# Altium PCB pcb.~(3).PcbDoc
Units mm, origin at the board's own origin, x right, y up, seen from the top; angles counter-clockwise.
Board outline 11.94 x 11.05 mm, 2 copper layers (Top Layer, Bottom Layer); 9 components, 6 nets, 43 pads, 0 vias.
Unrouted connection lines stored in the file: 24.
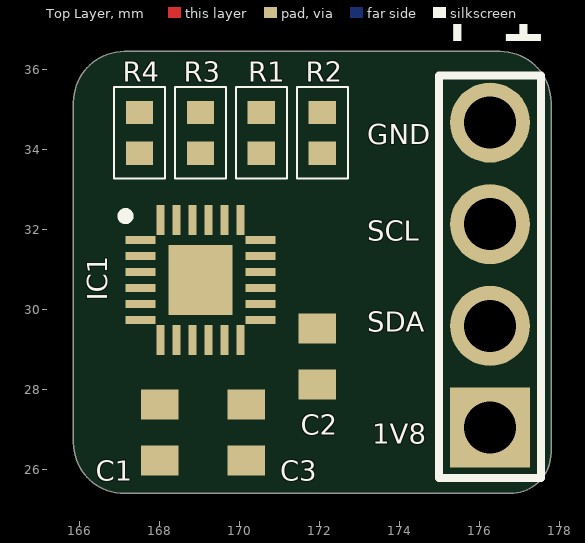
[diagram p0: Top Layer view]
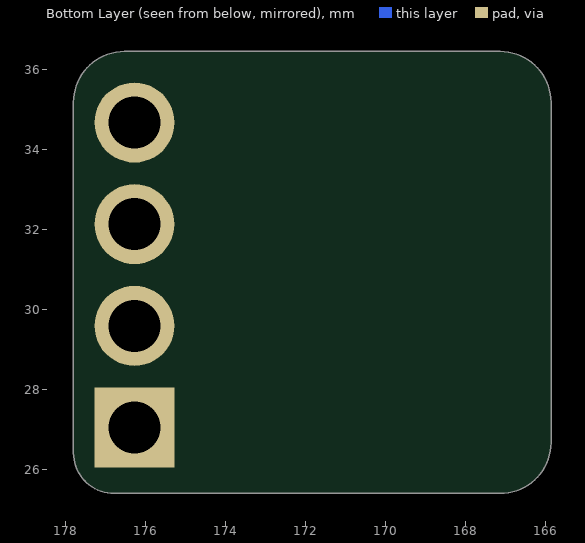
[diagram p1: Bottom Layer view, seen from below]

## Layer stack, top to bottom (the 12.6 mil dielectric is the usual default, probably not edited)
Top Solder: solder mask 0.0102, Solder Resist, Dk 3.5
Top Layer: signal copper 0.0356
Dielectric 1: dielectric 0.32, FR-4, Dk 4.8
Bottom Layer: signal copper 0.0356
Bottom Solder: solder mask 0.0102, Solder Resist, Dk 3.5

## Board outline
165.862,26.67 ccw(c167.132,26.67) 167.132,25.4 176.784,25.4 ccw(c176.784,26.416) 177.8,26.416 177.8,35.179 ccw(c176.53,35.179) 176.53,36.449 167.132,36.449 ccw(c167.132,35.179) 165.862,35.179

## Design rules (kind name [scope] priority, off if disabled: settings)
Clearance [All] p1: gap=0.254 ignorepadtopadclearanceinfootprint=FALSE
PolygonConnect [All] p1: connectstyle=Relief reliefconductorwidth=0.254 reliefentries=4 polygonreliefangle="90 Angle" airgapwidth=0.254
RoutingVias [All] p1: holewidth=0.711 width=1.27 viastyle="Through Hole" minholewidth=0.711 minwidth=1.27 maxholewidth=0.711 maxwidth=1.27
SolderMaskExpansion [All] p1: expansion=0.102 istentingtop=FALSE
SupplyNets "Schematic Supply Nets_1" [InNet('1V8')] p1: voltage=0.000
SupplyNets "Schematic Supply Nets" [InNet('GND')] p2: voltage=0.000
Width [All] p1: maxlimit=0.254 minlimit=0.254 preferedwidth=0.254
30 further rules are at their usual default settings.

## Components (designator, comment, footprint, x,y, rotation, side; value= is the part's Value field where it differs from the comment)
C1 "cap0603" CAPC1608X90N 168.021,26.924 r270 top
C2 "cap0603" CAPC1608X90N 171.958,28.829 r270 top
C3 "cap0603" CAPC1608X90N 170.18,26.924 r270 top
IC1 "ICM-20948" QFN40P300X300X105-25N-D 169.037,30.734 r0 top
P1 "Header 4" HDR1X4_DIA1.5 176.276,27.051 r90 top value=HDR4
R1 "res0402" 0402resistor 170.561,34.417 r270 top
R2 "res0402" 0402resistor 172.085,34.417 r270 top
R3 "res0402" 0402resistor 169.037,34.417 r270 top
R4 "res0402" 0402resistor 167.513,34.417 r90 top

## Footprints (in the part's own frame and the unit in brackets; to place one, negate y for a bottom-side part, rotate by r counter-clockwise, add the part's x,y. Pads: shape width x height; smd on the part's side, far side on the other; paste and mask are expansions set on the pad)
0402resistor [mil]
  rect 23x27 smd: 1(-20,0) 2(20,0)
  silkscreen extent -45,-25 45,25, body extent -20,-10 20,10, height 10
CAPC1608X90N [mm]
  rect 0.75x0.94 smd: 1(-0.7,0) 2(0.7,0)
  body extent -0.8,-0.45 0.8,0.45, height 0.8
HDR1X4_DIA1.5 [mm]
  rect 2x2 hole 1.3: 1(0,0)
  round 2 hole 1.3: 2(2.54,0) 3(5.08,0) 4(7.62,0)
  silkscreen extent -1.27,-1.27 8.8,1.27, body extent -0.5,-0.5 8.12,0.5, height 10
QFN40P300X300X105-25N-D [mm]
  rect 0.75x0.2 smd: 1(-1.5,1) 2(-1.5,0.6) 3(-1.5,0.2) 4(-1.5,-0.2) 5(-1.5,-0.6) 6(-1.5,-1) 13(1.5,-1) 14(1.5,-0.6) 15(1.5,-0.2) 16(1.5,0.2) 17(1.5,0.6) 18(1.5,1)
  rect 0.2x0.75 smd: 7(-1,-1.5) 8(-0.6,-1.5) 9(-0.2,-1.5) 10(0.2,-1.5) 11(0.6,-1.5) 12(1,-1.5) 19(1,1.5) 20(0.6,1.5) 21(0.2,1.5) 22(-0.2,1.5) 23(-0.6,1.5) 24(-1,1.5)
  rect 1.59x1.75 smd: 25(0,0)
  silkscreen extent -1.97,1.5 -1.78,1.7, body extent -1.5,-1.5 1.51,1.51, height 1

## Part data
C1 C2 C3: "Capacitor", Arrow Part Number=CL10A106KP8NNNC, Manufacturer_Name=SAMSUNG, Mouser Part Number=187-CL10A106KP8NNNC
IC1: "Integrated Circuit", Manufacturer_Name=TDK, Mouser Part Number=410-ICM-20948
P1: library part CMP-002-00093-3, "Header, 4-Pin"
R1 R2: Resistance=3k3
R3 R4: Resistance=10k

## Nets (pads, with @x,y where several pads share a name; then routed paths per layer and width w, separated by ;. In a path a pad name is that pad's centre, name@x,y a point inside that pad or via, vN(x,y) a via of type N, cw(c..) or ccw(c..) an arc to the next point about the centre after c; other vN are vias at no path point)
1V8: C1.1 C2.1 IC1.8 IC1.13 IC1.22 P1.1 R1.1 R2.1 R3.1
ADDRESS: IC1.9 R3.2 R4.1
GND: C1.2 C2.2 C3.2 IC1.11 IC1.12 IC1.18 IC1.20 IC1.25 P1.4 R4.2
NetC3_1: C3.1 IC1.10
SCL: IC1.23 P1.3 R1.2
SDA: IC1.24 P1.2 R2.2
pads on no net: IC1.1 IC1.2 IC1.3 IC1.4 IC1.5 IC1.6 IC1.7 IC1.14 IC1.15 IC1.16 IC1.17 IC1.19 IC1.21

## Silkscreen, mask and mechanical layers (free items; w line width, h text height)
Top Overlay:
  text "GND" at 173.201,34.136 h0.5
  text "SCL" at 173.201,31.723 h0.5
  text "SDA" at 173.201,29.437 h0.5
  text "1V8" at 173.328,26.643 h0.5
Mechanical 13:
  the board outline again, w0.102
